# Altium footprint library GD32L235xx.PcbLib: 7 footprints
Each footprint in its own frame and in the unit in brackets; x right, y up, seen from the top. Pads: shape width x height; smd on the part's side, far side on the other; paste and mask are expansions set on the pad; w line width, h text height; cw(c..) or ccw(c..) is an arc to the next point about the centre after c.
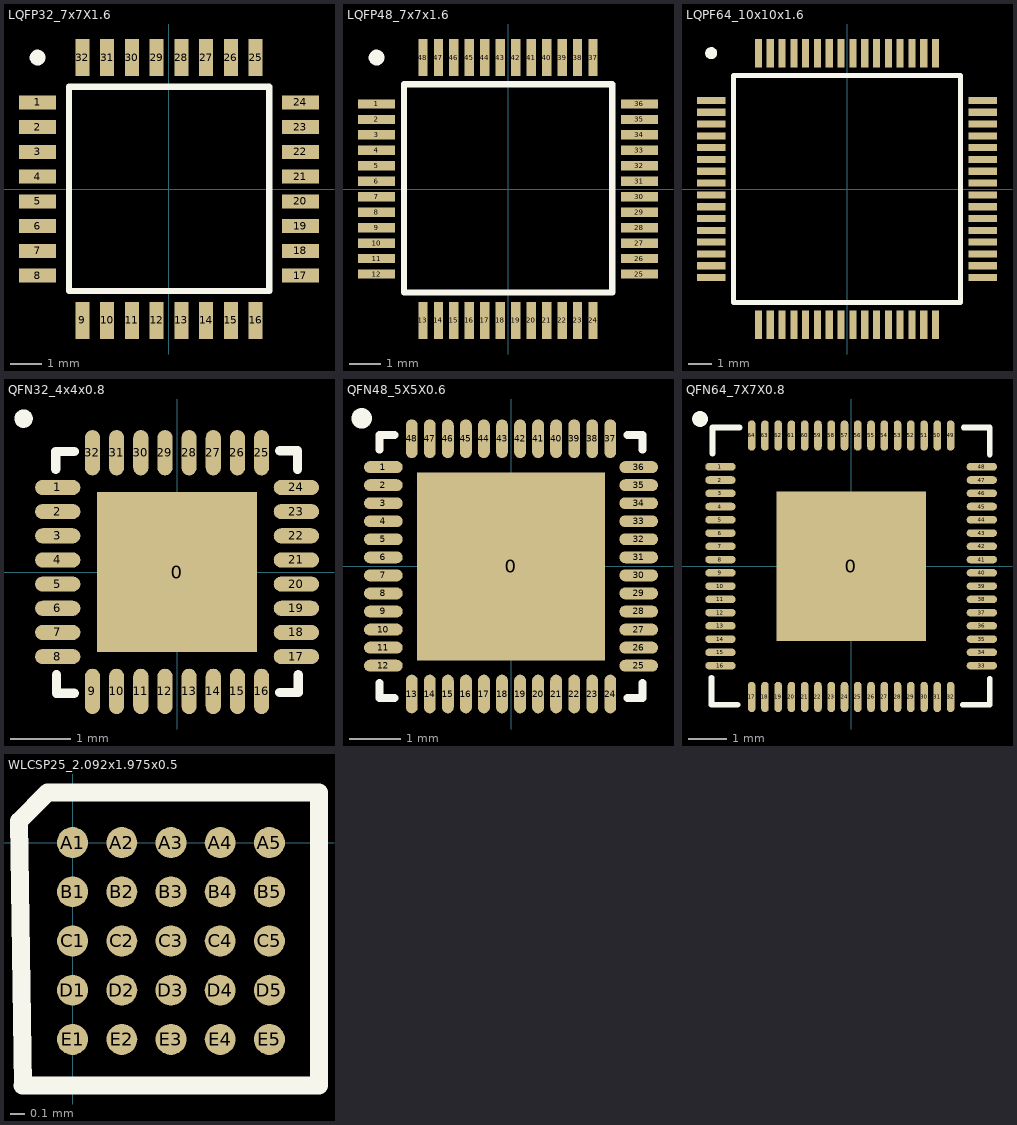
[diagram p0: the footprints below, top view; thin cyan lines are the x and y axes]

## LQFP32_7x7X1.6 [mm]
pads (32):
  rect 1.2x0.45 smd: 1(-4.25,2.8) 2(-4.25,2) 3(-4.25,1.2) 4(-4.25,0.4) 5(-4.25,-0.4) 6(-4.25,-1.2) 7(-4.25,-2) 8(-4.25,-2.8) 17(4.25,-2.8) 18(4.25,-2) 19(4.25,-1.2) 20(4.25,-0.4) 21(4.25,0.4) 22(4.25,1.2) 23(4.25,2) 24(4.25,2.8)
  rect 0.45x1.2 smd: 9(-2.8,-4.25) 10(-2,-4.25) 11(-1.2,-4.25) 12(-0.4,-4.25) 13(0.4,-4.25) 14(1.2,-4.25) 15(2,-4.25) 16(2.8,-4.25) 25(2.8,4.25) 26(2,4.25) 27(1.2,4.25) 28(0.4,4.25) 29(-0.4,4.25) 30(-1.2,4.25) 31(-2,4.25) 32(-2.8,4.25)
Top Overlay:
  circle w0.254: c-4.25,4.25 r0.127
  lines w0.203: -3.234,-3.296 -3.234,3.308 3.243,3.308 3.243,-3.296 -3.234,-3.296
3D body "TQFP80P900X900X160-32N.step": height 1.6, standoff 0, extent -4.5,-4.5 4.5,4.5

## LQFP48_7x7x1.6 [mm]
pads (48):
  rect 1.2x0.3 smd: 1(-4.25,2.75) 2(-4.25,2.25) 3(-4.25,1.75) 4(-4.25,1.25) 5(-4.25,0.75) 6(-4.25,0.25) 7(-4.25,-0.25) 8(-4.25,-0.75) 9(-4.25,-1.25) 10(-4.25,-1.75) 11(-4.25,-2.25) 12(-4.25,-2.75) 25(4.25,-2.75) 26(4.25,-2.25) 27(4.25,-1.75) 28(4.25,-1.25) 29(4.25,-0.75) 30(4.25,-0.25) 31(4.25,0.25) 32(4.25,0.75) 33(4.25,1.25) 34(4.25,1.75) 35(4.25,2.25) 36(4.25,2.75)
  rect 0.3x1.2 smd: 13(-2.75,-4.25) 14(-2.25,-4.25) 15(-1.75,-4.25) 16(-1.25,-4.25) 17(-0.75,-4.25) 18(-0.25,-4.25) 19(0.25,-4.25) 20(0.75,-4.25) 21(1.25,-4.25) 22(1.75,-4.25) 23(2.25,-4.25) 24(2.75,-4.25) 37(2.75,4.25) 38(2.25,4.25) 39(1.75,4.25) 40(1.25,4.25) 41(0.75,4.25) 42(0.25,4.25) 43(-0.25,4.25) 44(-0.75,4.25) 45(-1.25,4.25) 46(-1.75,4.25) 47(-2.25,4.25) 48(-2.75,4.25)
Top Overlay:
  circle w0.254: c-4.25,4.25 r0.127
  lines w0.203: -3.361,-3.346 -3.361,3.385 3.37,3.385 3.37,-3.346 -3.361,-3.346
3D body "TSQFP50P900X900X160-48N.step": height 1.6, standoff 0, extent -4.5,-4.5 4.5,4.5

## LQPF64_10x10x1.6 [mm]
pads (64):
  rect 1.2x0.3 smd: 1(-5.75,3.75) 2(-5.75,3.25) 3(-5.75,2.75) 4(-5.75,2.25) 5(-5.75,1.75) 6(-5.75,1.25) 7(-5.75,0.75) 8(-5.75,0.25) 9(-5.75,-0.25) 10(-5.75,-0.75) 11(-5.75,-1.25) 12(-5.75,-1.75) 13(-5.75,-2.25) 14(-5.75,-2.75) 15(-5.75,-3.25) 16(-5.75,-3.75) 33(5.75,-3.75) 34(5.75,-3.25) 35(5.75,-2.75) 36(5.75,-2.25) 37(5.75,-1.75) 38(5.75,-1.25) 39(5.75,-0.75) 40(5.75,-0.25) 41(5.75,0.25) 42(5.75,0.75) 43(5.75,1.25) 44(5.75,1.75) 45(5.75,2.25) 46(5.75,2.75) 47(5.75,3.25) 48(5.75,3.75)
  rect 0.3x1.2 smd: 17(-3.75,-5.75) 18(-3.25,-5.75) 19(-2.75,-5.75) 20(-2.25,-5.75) 21(-1.75,-5.75) 22(-1.25,-5.75) 23(-0.75,-5.75) 24(-0.25,-5.75) 25(0.25,-5.75) 26(0.75,-5.75) 27(1.25,-5.75) 28(1.75,-5.75) 29(2.25,-5.75) 30(2.75,-5.75) 31(3.25,-5.75) 32(3.75,-5.75) 49(3.75,5.75) 50(3.25,5.75) 51(2.75,5.75) 52(2.25,5.75) 53(1.75,5.75) 54(1.25,5.75) 55(0.75,5.75) 56(0.25,5.75) 57(-0.25,5.75) 58(-0.75,5.75) 59(-1.25,5.75) 60(-1.75,5.75) 61(-2.25,5.75) 62(-2.75,5.75) 63(-3.25,5.75) 64(-3.75,5.75)
Top Overlay:
  circle w0.254: c-5.75,5.75 r0.127
  lines w0.203: -4.801,-4.801 -4.801,4.801 4.801,4.801 4.801,-4.801 -4.801,-4.801
3D body "TSQFP50P1200X1200X160-64N.step": height 1.6, standoff 0, extent -6,-6 6,6

## QFN32_4x4x0.8 [mm]
pads (33):
  rect 2.65x2.65 smd: 0(0,0)
  oval 0.75x0.25 smd: 1(-1.975,1.4) 2(-1.975,1) 3(-1.975,0.6) 4(-1.975,0.2) 5(-1.975,-0.2) 6(-1.975,-0.6) 7(-1.975,-1) 8(-1.975,-1.4) 17(1.975,-1.4) 18(1.975,-1) 19(1.975,-0.6) 20(1.975,-0.2) 21(1.975,0.2) 22(1.975,0.6) 23(1.975,1) 24(1.975,1.4)
  oval 0.25x0.75 smd: 9(-1.4,-1.975) 10(-1,-1.975) 11(-0.6,-1.975) 12(-0.2,-1.975) 13(0.2,-1.975) 14(0.6,-1.975) 15(1,-1.975) 16(1.4,-1.975) 25(1.4,1.975) 26(1,1.975) 27(0.6,1.975) 28(0.2,1.975) 29(-0.2,1.975) 30(-0.6,1.975) 31(-1,1.975) 32(-1.4,1.975)
Top Overlay:
  circle w0.152: c-2.54,2.54 r0.076
  lines w0.152: -2.007,1.702 -2.007,1.993 -1.702,1.993 ; -1.993,-1.702 -1.993,-2.007 -1.702,-2.007 ; 1.702,-1.993 2.007,-1.993 2.007,-1.702 ; 1.702,2.007 1.993,2.007 1.993,1.702
3D body "QFN32_4x4x0.8.STEP": height 0.8, standoff 0, extent -2.051,-2.051 2.051,2.051

## QFN48_5X5X0.6 [mm]
pads (49):
  rect 3.65x3.65 smd: 0(0,0)
  oval 0.75x0.23 smd: 1(-2.475,1.925) 2(-2.475,1.575) 3(-2.475,1.225) 4(-2.475,0.875) 5(-2.475,0.525) 6(-2.475,0.175) 7(-2.475,-0.175) 8(-2.475,-0.525) 9(-2.475,-0.875) 10(-2.475,-1.225) 11(-2.475,-1.575) 12(-2.475,-1.925) 25(2.475,-1.925) 26(2.475,-1.575) 27(2.475,-1.225) 28(2.475,-0.875) 29(2.475,-0.525) 30(2.475,-0.175) 31(2.475,0.175) 32(2.475,0.525) 33(2.475,0.875) 34(2.475,1.225) 35(2.475,1.575) 36(2.475,1.925)
  oval 0.23x0.75 smd: 13(-1.925,-2.475) 14(-1.575,-2.475) 15(-1.225,-2.475) 16(-0.875,-2.475) 17(-0.525,-2.475) 18(-0.175,-2.475) 19(0.175,-2.475) 20(0.525,-2.475) 21(0.875,-2.475) 22(1.225,-2.475) 23(1.575,-2.475) 24(1.925,-2.475) 37(1.925,2.475) 38(1.575,2.475) 39(1.225,2.475) 40(0.875,2.475) 41(0.525,2.475) 42(0.175,2.475) 43(-0.175,2.475) 44(-0.525,2.475) 45(-0.875,2.475) 46(-1.225,2.475) 47(-1.575,2.475) 48(-1.925,2.475)
Top Overlay:
  circle w0.254: c-2.896,2.87 r0.072
  lines w0.152: -2.551,-2.261 -2.551,-2.551 -2.261,-2.551 ; -2.551,2.261 -2.551,2.551 -2.261,2.551 ; 2.261,-2.551 2.551,-2.551 2.551,-2.261 ; 2.261,2.551 2.551,2.551 2.551,2.261
3D body "QFN48_5X5X0.6.STEP": height 0.6, standoff 0, extent -2.551,-2.551 2.551,2.551

## QFN64_7X7X0.8 [mm]
pads (65):
  rect 3.95x3.95 smd: 0(0,0)
  oval 0.8x0.2 smd: 1(-3.45,2.625) 2(-3.45,2.275) 3(-3.45,1.925) 4(-3.45,1.575) 5(-3.45,1.225) 6(-3.45,0.875) 7(-3.45,0.525) 8(-3.45,0.175) 9(-3.45,-0.175) 10(-3.45,-0.525) 11(-3.45,-0.875) 12(-3.45,-1.225) 13(-3.45,-1.575) 14(-3.45,-1.925) 15(-3.45,-2.275) 16(-3.45,-2.625) 33(3.45,-2.625) 34(3.45,-2.275) 35(3.45,-1.925) 36(3.45,-1.575) 37(3.45,-1.225) 38(3.45,-0.875) 39(3.45,-0.525) 40(3.45,-0.175) 41(3.45,0.175) 42(3.45,0.525) 43(3.45,0.875) 44(3.45,1.225) 45(3.45,1.575) 46(3.45,1.925) 47(3.45,2.275) 48(3.45,2.625)
  oval 0.2x0.8 smd: 17(-2.625,-3.45) 18(-2.275,-3.45) 19(-1.925,-3.45) 20(-1.575,-3.45) 21(-1.225,-3.45) 22(-0.875,-3.45) 23(-0.525,-3.45) 24(-0.175,-3.45) 25(0.175,-3.45) 26(0.525,-3.45) 27(0.875,-3.45) 28(1.225,-3.45) 29(1.575,-3.45) 30(1.925,-3.45) 31(2.275,-3.45) 32(2.625,-3.45) 49(2.625,3.45) 50(2.275,3.45) 51(1.925,3.45) 52(1.575,3.45) 53(1.225,3.45) 54(0.875,3.45) 55(0.525,3.45) 56(0.175,3.45) 57(-0.175,3.45) 58(-0.525,3.45) 59(-0.875,3.45) 60(-1.225,3.45) 61(-1.575,3.45) 62(-1.925,3.45) 63(-2.275,3.45) 64(-2.625,3.45)
Top Overlay:
  circle w0.254: c-3.988,3.886 r0.08
  lines w0.152: -3.683,-2.946 -3.683,-3.658 -2.997,-3.658 ; -3.658,2.972 -3.658,3.658 -2.946,3.658 ; 2.946,-3.658 3.658,-3.658 3.658,-2.972 ; 2.972,3.658 3.658,3.658 3.658,2.946
3D body "QFN35P700X700X80_HS-65N.step": height 0.8, standoff 0, extent -3.551,-3.551 3.551,3.551
3D body "QFN35P700X700X80_HS-65N.step": height 0.8, standoff 0, extent -3.551,-3.551 3.551,3.551

## WLCSP25_2.092x1.975x0.5 [mm]
pads (25):
  round 0.22 smd mask+0.04: A1(0,0) A2(0.35,0) A3(0.7,0) A4(1.05,0) A5(1.4,0) B1(0,-0.35) B2(0.35,-0.35) B3(0.7,-0.35) B4(1.05,-0.35) B5(1.4,-0.35) C1(0,-0.7) C2(0.35,-0.7) C3(0.7,-0.7) C4(1.05,-0.7) C5(1.4,-0.7) D1(0,-1.05) D2(0.35,-1.05) D3(0.7,-1.05) D4(1.05,-1.05) D5(1.4,-1.05) E1(0,-1.4) E2(0.35,-1.4) E3(0.7,-1.4) E4(1.05,-1.4) E5(1.4,-1.4)
Top Overlay:
  lines w0.127: -0.356,-1.727 1.753,-1.727 1.753,0.356 -0.178,0.356 -0.381,0.152 -0.353,-1.727
3D body "BGA25C35P5X5_209X198X50.step": height 0.5, standoff 0, extent -0.345,-1.69 1.745,0.29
